// Mitsubishi GX Works2 project: 基本指令   PLC: FX3U/FX3UC

PROGRAM MAIN
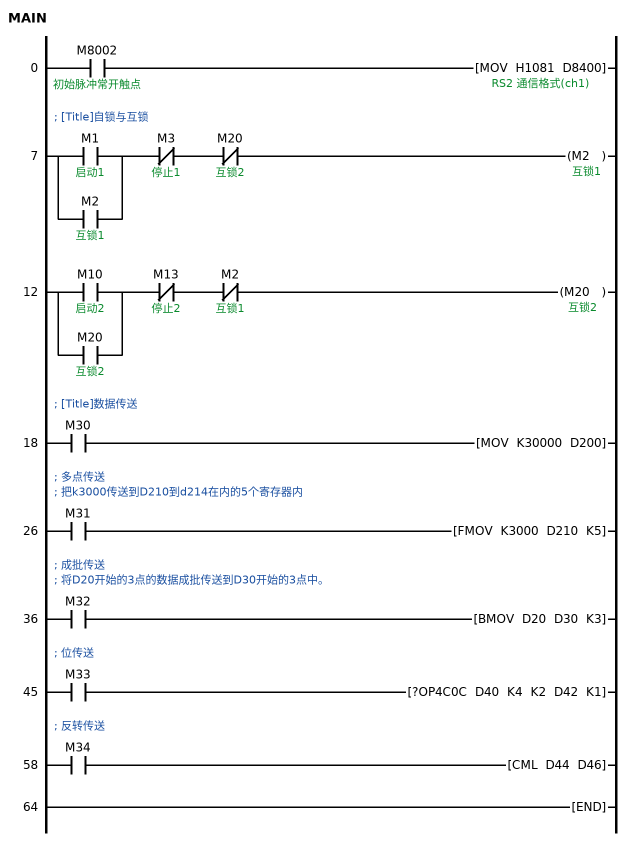
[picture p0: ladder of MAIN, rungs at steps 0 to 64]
0     LD      M8002  ; 初始脉冲常开触点
      MOV     H1081 D8400  ; RS2 通信格式(ch1)
; [Title]自锁与互锁
7     LD      M1  ; 启动1
      OR      M2  ; 互锁1
      ANI     M3  ; 停止1
      ANI     M20  ; 互锁2
      OUT     M2  ; 互锁1
12    LD      M10  ; 启动2
      OR      M20  ; 互锁2
      ANI     M13  ; 停止2
      ANI     M2  ; 互锁1
      OUT     M20  ; 互锁2
; [Title]数据传送
18    LD      M30
      MOV     K30000 D200
; 多点传送
; 把k3000传送到D210到d214在内的5个寄存器内
26    LD      M31
      FMOV    K3000 D210 K5
; 成批传送
; 将D20开始的3点的数据成批传送到D30开始的3点中。
36    LD      M32
      BMOV    D20 D30 K3
; 位传送
45    LD      M33
      ?OP4C0C D40 K4 K2 D42 K1
; 反转传送
58    LD      M34
      CML     D44 D46
64    END
END_PROGRAM

// device comments not shown above
C10  ; CCD1拍照连续不良计数
C11  ; CCD2连续不良计数
